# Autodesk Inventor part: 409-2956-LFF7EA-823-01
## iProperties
Created: 2010-11
Part Number: 409-2956-LFF7EA-823-01
Material: 3/8" OD TUBE - SS
Document SubType Name: Modeling
Designer: S. Boerckel
Engineer: Steve Boerckel
Mass: 468.349 g
Surface Area: 1014.84 cm^2
Volume: 57.9639 cm^3
Density: 8.08 g/cm^3
Description: PRESSURE DIFF TUBE
Length: 75.820 in
Author: S. Boerckel
Revision Number: 0
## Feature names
1. Sweep3
